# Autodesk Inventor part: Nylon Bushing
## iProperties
Shininess: 64.0
Length Units: 11272
Angle Units: 11279
Time Units: 11290
Mass Units: 11286
Length Display Precision: 3
Angle Display Precision: 2
Compacted: True
Part Number: Nylon Bushing
Document SubType Name: Modeling
Created: 2003-08
Designer: FT User
Manufacturer: Standard
Standards Organization: Custom
Density: 0.0
Volumn: 0.0
Area: 0.0
PropertySet Name: Model Information
Control State: 0
Master: False
Checked Out: False
Author: FT User
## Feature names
1. Extrusion1
